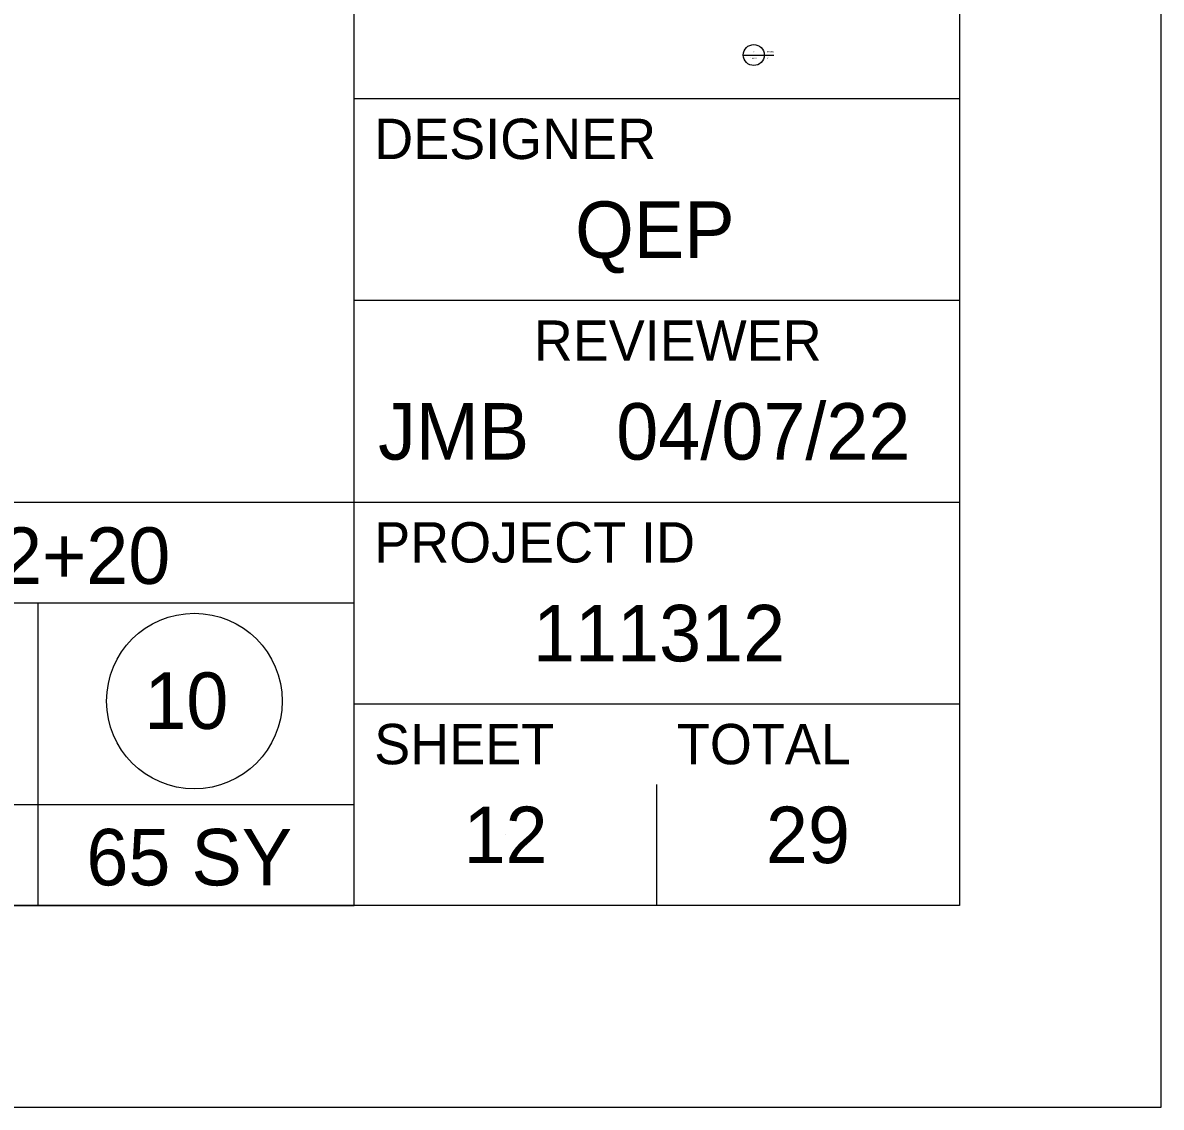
# Model space of a CAD drawing. Extents: x -34.1 to 34, y 0 to 22.
# Drawn here: x 31.179 to 34, y 0 to 2.688 of the extents above; entities that cross this region are included whole.
import ezdxf

# ---------------------------------------------------------------- set-up
doc = ezdxf.new("R2010")
doc.units = 0
for name, color, linetype in [('CS-ALGN-TEXT', 7, 'Continuous'), ('CS-ANNO', 7, 'Continuous'), ('CS-ANNO-MATC', 7, 'Continuous'), ('CS-ANNO-MATC-TEXT', 7, 'Continuous'), ('CS-ANNO-TABL', 7, 'Continuous')]:
    doc.layers.add(name, color=color, linetype=linetype)

msp = doc.modelspace()

# ---------------------------------------------------------------- linework, layer by layer
at = {"layer": 'CS-ALGN-TEXT'}
for p, q in [((29.0522, 1.5), (32, 1.5)), ((29.0522, 1.25), (32, 1.25)), ((31.2175, 0.5), (31.2175, 1.25)), ((32.75, 0.5), (32.75, 0.8)), ((29.0522, 0.75), (32, 0.75)), ((32.375, 0.675), (32.375, 0.675)), ((27.25, 0.5), (32, 0.5))]:
    msp.add_line(p, q, dxfattribs=at)
at = {"layer": 'CS-ANNO'}
msp.add_lwpolyline([(0, 0), (34, 0), (34, 22), (0, 22)], close=True, dxfattribs=at)
at = {"layer": 'CS-ANNO-MATC'}
for p, q in [((32, 0.5), (32, 21.5)), ((32, 2.5), (33.5, 2.5)), ((32, 2), (33.5, 2)), ((32, 1.5), (33.5, 1.5)), ((32, 1), (33.5, 1))]:
    msp.add_line(p, q, dxfattribs=at)
msp.add_lwpolyline([(1.5, 21.5), (33.5, 21.5), (33.5, 0.5), (1.5, 0.5)], close=True, dxfattribs=at)
at = {"layer": 'CS-ANNO-MATC-TEXT'}
msp.add_circle((31.6044, 1.0067), 0.2175, dxfattribs=at)
at = {"layer": 'CS-ANNO-TABL'}
for p, q in [((32.9644, 2.6078), (33.0165, 2.6078)), ((32.9907, 2.6078), (33.0402, 2.6078))]:
    msp.add_line(p, q, dxfattribs=at)
msp.add_circle((32.9905, 2.6078), 0.026, dxfattribs=at)

# ---------------------------------------------------------------- texts
at = {"layer": 'CS-ALGN-TEXT'}
for s, height, p in [('DESIGNER', 0.1, (32.05, 2.35)), ('QEP', 0.14, (32.5477, 2.105)), ('REVIEWER', 0.1, (32.4454, 1.85)), ('04/07/22', 0.14, (32.6497, 1.605)), ('JMB', 0.14, (32.0596, 1.605)), ('Sheet Totals 1+35 to 2+20', 0.14, (29.3382, 1.2971)), ('PROJECT ID', 0.1, (32.05, 1.35)), ('111312', 0.14, (32.4435, 1.105)), ('SHEET', 0.1, (32.05, 0.85)), ('TOTAL', 0.1, (32.8, 0.85)), ('12', 0.14, (32.2714, 0.605)), ('29', 0.14, (33.0206, 0.605))]:
    msp.add_text(s, height=height, dxfattribs=at).set_placement(p)
at = {"layer": 'CS-ANNO-MATC-TEXT'}
for s, p in [('10', (31.4804, 0.9376)), ('65 SY', (31.3368, 0.5498))]:
    msp.add_text(s, height=0.14, dxfattribs=at).set_placement(p)
at = {"layer": 'CS-ANNO-TABL'}
for s, p in [('2+00.00', (32.9825, 2.598)), ('2', (32.9893, 2.6144)), ('Drawing', (33.0232, 2.6144)), ('1:2', (33.0232, 2.598))]:
    msp.add_text(s, height=0.00328, dxfattribs=at).set_placement(p)

doc.saveas('drawing.dxf')
